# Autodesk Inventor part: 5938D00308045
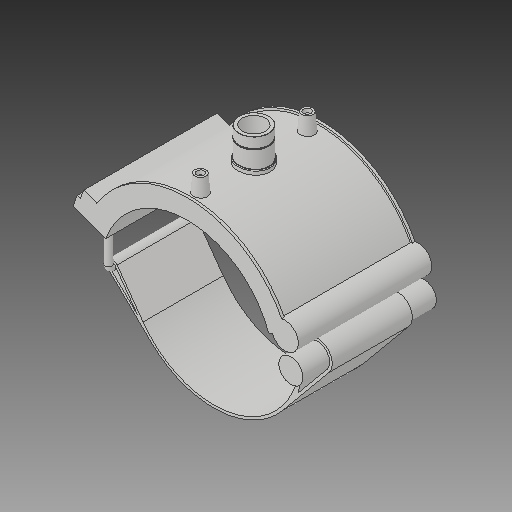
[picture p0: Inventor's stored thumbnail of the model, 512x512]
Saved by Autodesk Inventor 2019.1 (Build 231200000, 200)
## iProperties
Created: 2017-07
Part Number: 5938D00308045
Material: Generic
Description: PLASSON TRANSITION SADDLE 8''DIPS x 1"NPT
Document SubType Name: Modeling
Designer: KIM
Density: 1 g/cm^3
Appearance: Default
Author: KIM
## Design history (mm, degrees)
derived "5938D.ipt"
feature "Solid1::5938D.ipt"
tag "TaggingFeature1"
body "Solid1"
other parameters: "d0" = 228.9, "d1" = 274.68, "d2" = 449.58, "d3" = 57.225, "d4" = 176.022, "d5" = 0, "d40" = 142.8336, "d41" = 42.4074, "d43" = 0, "d45" = 0, "d47" = 179.25, "d48" = 39.3783, "d50" = 0, "d78" = 159.34, "d79" = 15, "d80" = 70.4088, "d82" = 5 deg, "d84" = 4, "d85" = 14, "d86" = 0, "d87" = 3, "d88" = 0, "d96" = 280.1736, "d97" = 3.52044, "d98" = 0, "d102" = 0.90873, "d103" = 30.291, "d104" = 25.146, "d105" = 0, "d106" = 24.2328, "d108" = 0, "d109" = -13.97, "d111" = 0.5, "d112" = 0.5, "d113" = 0, "d114" = 0.5, "d117" = 0.30291, "d120" = 140 deg, "d121" = 24.228, "d122" = 20 deg, "d123" = 1098.72, "d124" = 164.808, "d126" = 0, "d143" = 235.767, "d145" = 35.21538, "d149" = 3.4335, "d150" = 38.73692, "d153" = 176.022, "d154" = 0, "d156" = 137.34, "d157" = 160 deg, "d159" = 9.156, "d161" = 3.4335, "d162" = 105.6132, "d163" = 0, "d164" = 114.45, "d167" = 22.89, "d168" = 133.99024, "d170" = 3.4335, "d172" = 0, "d173" = 1, "d175" = 114.45, "d176" = 20 deg, "d177" = 16.023, "d178" = 45.78, "d180" = 0, "d183" = 18.312, "d184" = 12.8184, "d185" = 57.20715, "d186" = 57.20715, "d187" = 137.34, "d188" = 13.734, "d189" = 16.023, "d190" = 0, "d191" = 164.808, "d193" = 9.156, "d194" = 4.69245, "d195" = 90 deg, "d197" = 0, "d199" = 0, "d_" = 228.9, "B_" = 179.832, "H_" = 41.91, "L_" = 176.022, "d_t" = 6, "G_" = 30.291, "d148" = 3.4335, "d160" = 3.4335, "d169" = 3.4335, "d192" = 9.156
